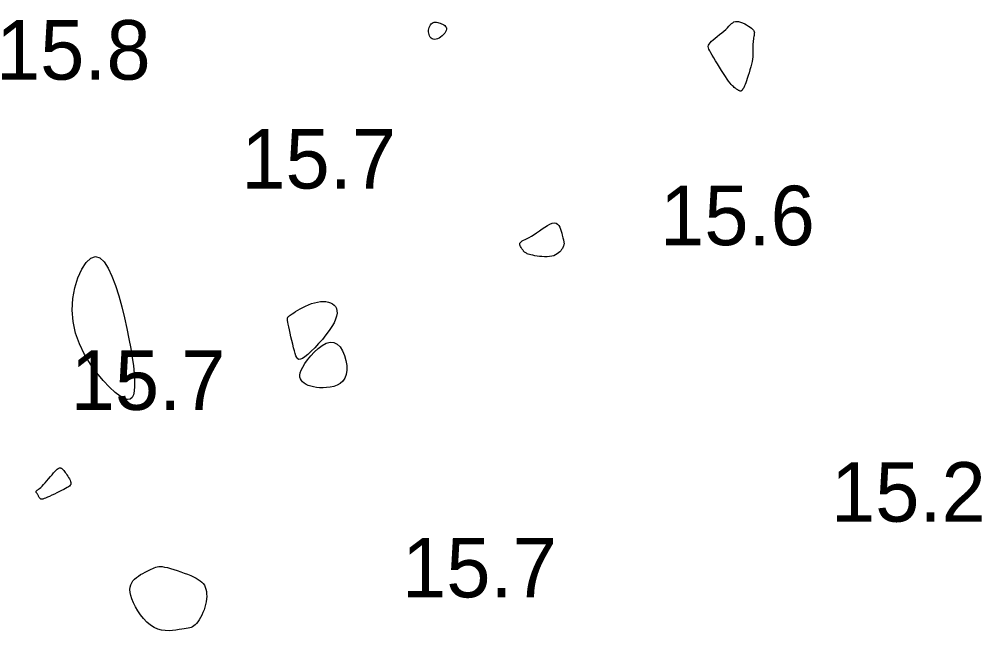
# Model space of a CAD drawing. Extents: x 3040093 to 3056816, y 408076 to 509144.
# Drawn here: x 3045759.4 to 3045840.4, y 434288 to 434339.4 of the extents above; entities that cross this region are included whole.
import ezdxf

# ---------------------------------------------------------------- set-up
doc = ezdxf.new("R2010")
doc.units = 0
doc.layers.add('V-CHAN-CONT-EL17', color=7, linetype='Continuous')
doc.layers.add('V-TOPO-SOUN-0610', color=7, linetype='Continuous')

msp = doc.modelspace()

# ---------------------------------------------------------------- linework, layer by layer
at = {"layer": 'V-CHAN-CONT-EL17'}
for points in [[(3045794.228, 434339.085), (3045794.32, 434339.11), (3045794.417, 434339.118), (3045794.519, 434339.111), (3045794.623, 434339.09), (3045794.728, 434339.06), (3045794.833, 434339.021), (3045794.936, 434338.977), (3045795.035, 434338.929), (3045795.126, 434338.876), (3045795.208, 434338.818), (3045795.276, 434338.754), (3045795.326, 434338.683), (3045795.355, 434338.604), (3045795.361, 434338.515), (3045795.338, 434338.416), (3045795.286, 434338.307), (3045795.208, 434338.192), (3045795.109, 434338.076), (3045794.995, 434337.964), (3045794.869, 434337.863), (3045794.738, 434337.776), (3045794.606, 434337.71), (3045794.478, 434337.669), (3045794.359, 434337.657), (3045794.25, 434337.673), (3045794.153, 434337.714), (3045794.068, 434337.776), (3045793.995, 434337.856), (3045793.937, 434337.952), (3045793.893, 434338.061), (3045793.864, 434338.178), (3045793.852, 434338.302), (3045793.855, 434338.428), (3045793.873, 434338.553), (3045793.904, 434338.673), (3045793.947, 434338.786), (3045794.002, 434338.887), (3045794.068, 434338.972), (3045794.144, 434339.039)], [(3045819.619, 434333.577), (3045819.551, 434333.63), (3045819.476, 434333.693), (3045819.393, 434333.772), (3045819.301, 434333.87), (3045819.198, 434333.993), (3045819.081, 434334.144), (3045818.95, 434334.327), (3045818.803, 434334.546), (3045818.644, 434334.792), (3045818.478, 434335.057), (3045818.309, 434335.332), (3045818.141, 434335.608), (3045817.981, 434335.875), (3045817.831, 434336.125), (3045817.697, 434336.349), (3045817.582, 434336.539), (3045817.49, 434336.699), (3045817.423, 434336.837), (3045817.381, 434336.956), (3045817.368, 434337.064), (3045817.384, 434337.167), (3045817.432, 434337.271), (3045817.515, 434337.381), (3045817.631, 434337.503), (3045817.777, 434337.635), (3045817.943, 434337.775), (3045818.123, 434337.92), (3045818.31, 434338.068), (3045818.496, 434338.217), (3045818.673, 434338.365), (3045818.835, 434338.508), (3045818.977, 434338.644), (3045819.101, 434338.771), (3045819.212, 434338.886), (3045819.317, 434338.985), (3045819.42, 434339.066), (3045819.528, 434339.126), (3045819.644, 434339.163), (3045819.775, 434339.172), (3045819.923, 434339.154), (3045820.086, 434339.111), (3045820.256, 434339.047), (3045820.428, 434338.969), (3045820.595, 434338.881), (3045820.752, 434338.787), (3045820.892, 434338.693), (3045821.009, 434338.603), (3045821.1, 434338.521), (3045821.165, 434338.446), (3045821.208, 434338.375), (3045821.232, 434338.305), (3045821.242, 434338.235), (3045821.239, 434338.162), (3045821.229, 434338.082), (3045821.213, 434337.994), (3045821.196, 434337.897), (3045821.178, 434337.789), (3045821.16, 434337.674), (3045821.144, 434337.553), (3045821.129, 434337.428), (3045821.117, 434337.299), (3045821.109, 434337.17), (3045821.106, 434337.04), (3045821.107, 434336.912), (3045821.111, 434336.783), (3045821.115, 434336.649), (3045821.118, 434336.508), (3045821.115, 434336.356), (3045821.104, 434336.192), (3045821.084, 434336.01), (3045821.051, 434335.809), (3045821.004, 434335.587), (3045820.944, 434335.349), (3045820.876, 434335.103), (3045820.802, 434334.857), (3045820.726, 434334.617), (3045820.65, 434334.391), (3045820.579, 434334.186), (3045820.514, 434334.009), (3045820.46, 434333.867), (3045820.414, 434333.755), (3045820.376, 434333.67), (3045820.345, 434333.606), (3045820.319, 434333.559), (3045820.297, 434333.524), (3045820.278, 434333.497), (3045820.261, 434333.472), (3045820.244, 434333.446), (3045820.227, 434333.419), (3045820.209, 434333.393), (3045820.19, 434333.369), (3045820.168, 434333.348), (3045820.144, 434333.332), (3045820.116, 434333.321), (3045820.084, 434333.318), (3045820.047, 434333.323), (3045820.006, 434333.336), (3045819.961, 434333.355), (3045819.912, 434333.381), (3045819.86, 434333.413), (3045819.804, 434333.448), (3045819.745, 434333.488), (3045819.684, 434333.531)], [(3045801.667, 434320.124), (3045801.625, 434320.188), (3045801.586, 434320.255), (3045801.553, 434320.326), (3045801.532, 434320.397), (3045801.525, 434320.468), (3045801.539, 434320.537), (3045801.576, 434320.603), (3045801.64, 434320.664), (3045801.731, 434320.724), (3045801.846, 434320.786), (3045801.984, 434320.854), (3045802.142, 434320.932), (3045802.318, 434321.023), (3045802.511, 434321.13), (3045802.719, 434321.258), (3045802.939, 434321.408), (3045803.167, 434321.571), (3045803.397, 434321.737), (3045803.626, 434321.896), (3045803.848, 434322.037), (3045804.058, 434322.15), (3045804.252, 434322.225), (3045804.424, 434322.251), (3045804.572, 434322.22), (3045804.696, 434322.141), (3045804.799, 434322.024), (3045804.883, 434321.878), (3045804.952, 434321.715), (3045805.008, 434321.546), (3045805.054, 434321.38), (3045805.092, 434321.227), (3045805.124, 434321.098), (3045805.151, 434320.989), (3045805.174, 434320.899), (3045805.193, 434320.823), (3045805.208, 434320.759), (3045805.22, 434320.702), (3045805.229, 434320.651), (3045805.235, 434320.602), (3045805.239, 434320.551), (3045805.239, 434320.498), (3045805.234, 434320.442), (3045805.224, 434320.382), (3045805.206, 434320.317), (3045805.18, 434320.247), (3045805.145, 434320.171), (3045805.099, 434320.088), (3045805.041, 434319.998), (3045804.97, 434319.904), (3045804.885, 434319.809), (3045804.785, 434319.717), (3045804.668, 434319.631), (3045804.535, 434319.553), (3045804.384, 434319.488), (3045804.213, 434319.44), (3045804.023, 434319.409), (3045803.818, 434319.395), (3045803.605, 434319.395), (3045803.388, 434319.408), (3045803.174, 434319.429), (3045802.969, 434319.457), (3045802.777, 434319.49), (3045802.605, 434319.524), (3045802.458, 434319.558), (3045802.333, 434319.592), (3045802.229, 434319.624), (3045802.143, 434319.656), (3045802.073, 434319.688), (3045802.016, 434319.718), (3045801.969, 434319.748), (3045801.931, 434319.777), (3045801.898, 434319.805), (3045801.87, 434319.834), (3045801.845, 434319.864), (3045801.821, 434319.896), (3045801.796, 434319.931), (3045801.77, 434319.971), (3045801.74, 434320.016), (3045801.706, 434320.066)], [(3045763.892, 434314.923), (3045763.952, 434315.887), (3045764.121, 434316.802), (3045764.376, 434317.634), (3045764.697, 434318.347), (3045765.063, 434318.904), (3045765.453, 434319.271), (3045765.845, 434319.411), (3045766.222, 434319.301), (3045766.58, 434318.966), (3045766.918, 434318.442), (3045767.235, 434317.765), (3045767.531, 434316.973), (3045767.805, 434316.102), (3045768.056, 434315.188), (3045768.284, 434314.268), (3045768.488, 434313.373), (3045768.666, 434312.516), (3045768.818, 434311.702), (3045768.943, 434310.939), (3045769.038, 434310.233), (3045769.104, 434309.591), (3045769.138, 434309.019), (3045769.139, 434308.524), (3045769.106, 434308.112), (3045769.034, 434307.79), (3045768.919, 434307.561), (3045768.754, 434307.431), (3045768.536, 434307.405), (3045768.258, 434307.489), (3045767.917, 434307.687), (3045767.507, 434308.005), (3045767.028, 434308.445), (3045766.503, 434308.996), (3045765.961, 434309.647), (3045765.428, 434310.385), (3045764.934, 434311.196), (3045764.506, 434312.069), (3045764.172, 434312.99), (3045763.961, 434313.947)], [(3045782.51, 434311.76), (3045782.437, 434312.05), (3045782.361, 434312.355), (3045782.286, 434312.664), (3045782.214, 434312.967), (3045782.148, 434313.253), (3045782.091, 434313.512), (3045782.045, 434313.734), (3045782.013, 434313.911), (3045781.994, 434314.047), (3045781.985, 434314.147), (3045781.985, 434314.219), (3045781.993, 434314.267), (3045782.006, 434314.299), (3045782.022, 434314.321), (3045782.041, 434314.339), (3045782.061, 434314.358), (3045782.085, 434314.381), (3045782.116, 434314.41), (3045782.159, 434314.446), (3045782.217, 434314.491), (3045782.294, 434314.547), (3045782.393, 434314.616), (3045782.519, 434314.699), (3045782.674, 434314.798), (3045782.854, 434314.908), (3045783.057, 434315.024), (3045783.277, 434315.143), (3045783.512, 434315.258), (3045783.757, 434315.366), (3045784.007, 434315.461), (3045784.26, 434315.539), (3045784.512, 434315.596), (3045784.757, 434315.629), (3045784.994, 434315.641), (3045785.219, 434315.628), (3045785.427, 434315.593), (3045785.617, 434315.533), (3045785.783, 434315.45), (3045785.923, 434315.341), (3045786.034, 434315.208), (3045786.111, 434315.05), (3045786.153, 434314.865), (3045786.157, 434314.654), (3045786.119, 434314.417), (3045786.036, 434314.152), (3045785.906, 434313.859), (3045785.726, 434313.539), (3045785.496, 434313.191), (3045785.224, 434312.827), (3045784.925, 434312.459), (3045784.611, 434312.099), (3045784.294, 434311.76), (3045783.987, 434311.454), (3045783.703, 434311.193), (3045783.454, 434310.99), (3045783.249, 434310.854), (3045783.086, 434310.783), (3045782.957, 434310.774), (3045782.855, 434310.822), (3045782.773, 434310.922), (3045782.704, 434311.07), (3045782.642, 434311.263), (3045782.579, 434311.494)], [(3045783.157, 434308.997), (3045783.081, 434309.133), (3045783.038, 434309.286), (3045783.033, 434309.46), (3045783.068, 434309.657), (3045783.146, 434309.881), (3045783.271, 434310.134), (3045783.446, 434310.419), (3045783.672, 434310.736), (3045783.94, 434311.068), (3045784.241, 434311.393), (3045784.565, 434311.692), (3045784.901, 434311.943), (3045785.238, 434312.126), (3045785.568, 434312.219), (3045785.878, 434312.203), (3045786.161, 434312.064), (3045786.41, 434311.819), (3045786.621, 434311.493), (3045786.789, 434311.11), (3045786.909, 434310.694), (3045786.976, 434310.27), (3045786.985, 434309.863), (3045786.932, 434309.497), (3045786.815, 434309.192), (3045786.64, 434308.946), (3045786.419, 434308.754), (3045786.162, 434308.61), (3045785.879, 434308.508), (3045785.581, 434308.441), (3045785.278, 434308.404), (3045784.979, 434308.391), (3045784.695, 434308.398), (3045784.428, 434308.421), (3045784.179, 434308.461), (3045783.95, 434308.516), (3045783.742, 434308.586), (3045783.558, 434308.67), (3045783.398, 434308.767), (3045783.263, 434308.876)], [(3045761.145, 434299.145), (3045761.121, 434299.185), (3045761.096, 434299.228), (3045761.07, 434299.272), (3045761.044, 434299.318), (3045761.018, 434299.364), (3045760.991, 434299.409), (3045760.964, 434299.453), (3045760.937, 434299.494), (3045760.912, 434299.533), (3045760.889, 434299.57), (3045760.87, 434299.604), (3045760.856, 434299.636), (3045760.849, 434299.665), (3045760.849, 434299.691), (3045760.857, 434299.714), (3045760.876, 434299.735), (3045760.906, 434299.757), (3045760.947, 434299.784), (3045761.001, 434299.819), (3045761.067, 434299.866), (3045761.148, 434299.93), (3045761.243, 434300.014), (3045761.353, 434300.121), (3045761.479, 434300.254), (3045761.616, 434300.408), (3045761.761, 434300.575), (3045761.91, 434300.749), (3045762.057, 434300.922), (3045762.199, 434301.088), (3045762.332, 434301.24), (3045762.451, 434301.37), (3045762.553, 434301.473), (3045762.639, 434301.55), (3045762.712, 434301.605), (3045762.773, 434301.641), (3045762.825, 434301.66), (3045762.869, 434301.665), (3045762.909, 434301.659), (3045762.945, 434301.646), (3045762.981, 434301.628), (3045763.017, 434301.603), (3045763.054, 434301.572), (3045763.094, 434301.533), (3045763.138, 434301.484), (3045763.187, 434301.426), (3045763.241, 434301.357), (3045763.303, 434301.276), (3045763.372, 434301.182), (3045763.445, 434301.078), (3045763.52, 434300.968), (3045763.591, 434300.854), (3045763.657, 434300.74), (3045763.712, 434300.629), (3045763.753, 434300.524), (3045763.777, 434300.428), (3045763.781, 434300.344), (3045763.763, 434300.269), (3045763.723, 434300.201), (3045763.662, 434300.136), (3045763.577, 434300.072), (3045763.469, 434300.005), (3045763.338, 434299.933), (3045763.183, 434299.853), (3045763.005, 434299.762), (3045762.809, 434299.664), (3045762.603, 434299.561), (3045762.394, 434299.459), (3045762.187, 434299.36), (3045761.991, 434299.268), (3045761.811, 434299.188), (3045761.656, 434299.122), (3045761.529, 434299.074), (3045761.429, 434299.042), (3045761.352, 434299.026), (3045761.294, 434299.023), (3045761.25, 434299.032), (3045761.217, 434299.05), (3045761.192, 434299.076), (3045761.169, 434299.108)], [(3045770.463, 434288.451), (3045770.169, 434288.703), (3045769.892, 434288.995), (3045769.635, 434289.315), (3045769.404, 434289.652), (3045769.202, 434289.993), (3045769.033, 434290.328), (3045768.901, 434290.644), (3045768.81, 434290.932), (3045768.758, 434291.193), (3045768.742, 434291.428), (3045768.762, 434291.641), (3045768.813, 434291.833), (3045768.893, 434292.008), (3045769, 434292.167), (3045769.133, 434292.313), (3045769.286, 434292.448), (3045769.457, 434292.574), (3045769.639, 434292.689), (3045769.827, 434292.796), (3045770.016, 434292.894), (3045770.2, 434292.983), (3045770.373, 434293.065), (3045770.531, 434293.139), (3045770.67, 434293.205), (3045770.795, 434293.263), (3045770.914, 434293.31), (3045771.033, 434293.345), (3045771.161, 434293.366), (3045771.303, 434293.371), (3045771.468, 434293.36), (3045771.663, 434293.329), (3045771.892, 434293.279), (3045772.151, 434293.211), (3045772.43, 434293.129), (3045772.722, 434293.035), (3045773.019, 434292.933), (3045773.312, 434292.826), (3045773.594, 434292.717), (3045773.857, 434292.608), (3045774.094, 434292.503), (3045774.304, 434292.399), (3045774.49, 434292.293), (3045774.651, 434292.183), (3045774.789, 434292.066), (3045774.905, 434291.938), (3045775.001, 434291.798), (3045775.077, 434291.642), (3045775.134, 434291.469), (3045775.173, 434291.28), (3045775.195, 434291.078), (3045775.199, 434290.865), (3045775.186, 434290.644), (3045775.157, 434290.417), (3045775.111, 434290.187), (3045775.05, 434289.957), (3045774.974, 434289.729), (3045774.885, 434289.507), (3045774.786, 434289.293), (3045774.679, 434289.092), (3045774.567, 434288.905), (3045774.452, 434288.738), (3045774.337, 434288.593), (3045774.224, 434288.473), (3045774.115, 434288.38), (3045774.006, 434288.312), (3045773.893, 434288.262), (3045773.771, 434288.225), (3045773.636, 434288.198), (3045773.482, 434288.174), (3045773.306, 434288.148), (3045773.103, 434288.116), (3045772.87, 434288.075), (3045772.61, 434288.032), (3045772.328, 434287.996), (3045772.03, 434287.976), (3045771.72, 434287.983), (3045771.403, 434288.024), (3045771.085, 434288.111), (3045770.77, 434288.251)]]:
    msp.add_lwpolyline(points, close=True, dxfattribs=at)

# ---------------------------------------------------------------- texts
at = {"layer": 'V-TOPO-SOUN-0610'}
for s, p in [('15.8 ', (3045757.473, 434334.28)), ('15.7 ', (3045778.103, 434325.13)), ('15.6 ', (3045813.313, 434320.37)), ('15.7 ', (3045763.763, 434306.53)), ('15.2 ', (3045827.683, 434297.14)), ('15.7 ', (3045791.623, 434290.78))]:
    msp.add_text(s, height=5, dxfattribs=at).set_placement(p)

doc.saveas('drawing.dxf')
